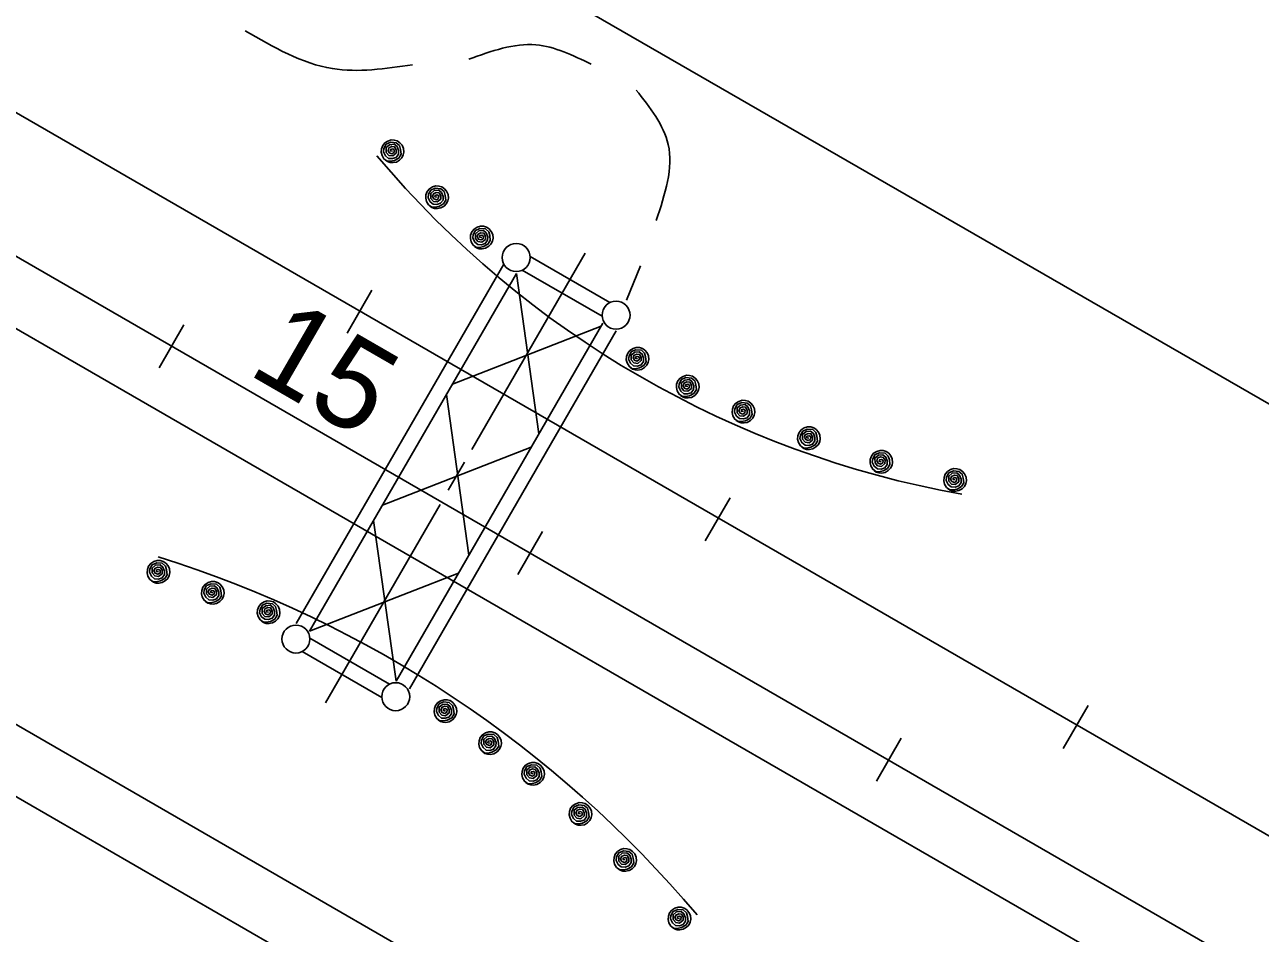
# Model space of a CAD drawing. Extents: x 36 to 2622, y -5330 to 219.
# Drawn here: x 617.89 to 659.11, y -5106.98 to -5076.66 of the extents above; entities that cross this region are included whole.
import ezdxf

# ---------------------------------------------------------------- set-up
doc = ezdxf.new("R2010")
doc.units = 0
doc.layers.add('2', color=7, linetype='Continuous')

msp = doc.modelspace()

# ---------------------------------------------------------------- linework, layer by layer
at = {"layer": '2'}
for p, q in [((699.623, -5134.156), (428.193, -4977.446)), ((700.667, -5132.348), (434.985, -4978.962)), ((693.9, -5144.068), (416.962, -4984.173)), ((692.86, -5145.872), (414.78, -4985.319)), ((661.896, -5090.759), (614.012, -5063.109)), ((702.741, -5128.756), (615.251, -5078.236)), ((636.594, -5084.285), (632.808, -5090.834)), ((637.414, -5085.931), (634.758, -5084.4)), ((626.948, -5096.646), (633.875, -5084.647)), ((637.154, -5086.382), (634.493, -5084.849)), ((638.44, -5084.703), (637.971, -5085.852)), ((627.398, -5096.902), (634.296, -5084.957)), ((634.296, -5084.957), (635.044, -5090.316)), ((628.644, -5086.956), (629.476, -5085.521)), ((622.378, -5088.111), (623.204, -5086.677)), ((630.281, -5098.566), (637.179, -5086.619)), ((630.73, -5098.824), (637.628, -5086.879)), ((632.161, -5088.654), (637.123, -5086.717)), ((631.96, -5089.001), (632.708, -5094.36)), ((629.825, -5092.695), (634.787, -5090.761)), ((632.563, -5091.262), (632.024, -5092.194)), ((631.754, -5092.668), (627.932, -5099.284)), ((640.592, -5093.883), (641.424, -5092.448)), ((629.532, -5093.209), (630.281, -5098.566)), ((634.344, -5095.007), (635.169, -5093.573)), ((627.398, -5096.902), (632.359, -5094.967)), ((630.065, -5098.664), (627.406, -5097.131)), ((629.804, -5099.113), (627.146, -5097.58)), ((652.541, -5100.81), (653.373, -5099.375)), ((646.311, -5101.903), (647.137, -5100.469))]:
    msp.add_line(p, q, dxfattribs=at)
for points in [[(630.162, -5080.884), (630.094, -5080.869), (630.098, -5080.822), (630.171, -5080.805), (630.223, -5080.84), (630.214, -5080.923), (630.139, -5080.965), (630.056, -5080.934), (630.013, -5080.855), (630.042, -5080.77), (630.137, -5080.726), (630.229, -5080.738), (630.287, -5080.834), (630.285, -5080.946), (630.168, -5081.04), (630.04, -5081.021), (629.954, -5080.922), (629.952, -5080.759), (630.067, -5080.663), (630.219, -5080.651), (630.314, -5080.728), (630.364, -5080.859), (630.362, -5080.976), (630.283, -5081.086), (630.16, -5081.127), (630.033, -5081.119), (629.929, -5081.034), (629.863, -5080.899), (629.877, -5080.786), (629.956, -5080.647), (630.104, -5080.582), (630.289, -5080.599), (630.397, -5080.695), (630.433, -5080.822), (630.452, -5080.982), (630.372, -5081.109), (630.227, -5081.188), (630.085, -5081.217), (629.977, -5081.207), (629.877, -5081.136), (629.813, -5081.025), (629.788, -5080.915), (629.794, -5080.805), (629.834, -5080.695), (629.909, -5080.603), (630.01, -5080.541), (630.121, -5080.505), (630.223, -5080.51), (630.322, -5080.539), (630.41, -5080.599), (630.481, -5080.684), (630.53, -5080.788), (630.541, -5080.911), (630.522, -5081.003), (630.472, -5081.102), (630.397, -5081.177), (630.291, -5081.242), (630.177, -5081.263), (630.083, -5081.258), (629.994, -5081.229), (629.925, -5081.179)], [(631.648, -5082.417), (631.579, -5082.403), (631.583, -5082.355), (631.656, -5082.338), (631.708, -5082.373), (631.7, -5082.457), (631.625, -5082.498), (631.542, -5082.467), (631.498, -5082.388), (631.527, -5082.303), (631.623, -5082.259), (631.714, -5082.271), (631.772, -5082.367), (631.77, -5082.48), (631.654, -5082.573), (631.525, -5082.554), (631.44, -5082.455), (631.438, -5082.292), (631.552, -5082.197), (631.704, -5082.184), (631.799, -5082.261), (631.849, -5082.392), (631.847, -5082.509), (631.768, -5082.619), (631.645, -5082.66), (631.519, -5082.652), (631.415, -5082.567), (631.348, -5082.432), (631.363, -5082.319), (631.442, -5082.18), (631.589, -5082.115), (631.774, -5082.132), (631.883, -5082.228), (631.918, -5082.355), (631.937, -5082.515), (631.858, -5082.642), (631.712, -5082.721), (631.571, -5082.75), (631.462, -5082.74), (631.363, -5082.669), (631.298, -5082.559), (631.273, -5082.448), (631.279, -5082.338), (631.319, -5082.228), (631.394, -5082.136), (631.496, -5082.074), (631.606, -5082.038), (631.708, -5082.043), (631.808, -5082.072), (631.895, -5082.132), (631.966, -5082.217), (632.016, -5082.322), (632.026, -5082.444), (632.008, -5082.536), (631.957, -5082.636), (631.883, -5082.711), (631.777, -5082.775), (631.662, -5082.796), (631.568, -5082.792), (631.479, -5082.762), (631.41, -5082.713)], [(633.137, -5083.761), (633.068, -5083.746), (633.072, -5083.699), (633.145, -5083.682), (633.197, -5083.717), (633.189, -5083.801), (633.114, -5083.842), (633.031, -5083.811), (632.987, -5083.732), (633.016, -5083.646), (633.112, -5083.603), (633.204, -5083.615), (633.262, -5083.711), (633.26, -5083.823), (633.143, -5083.917), (633.014, -5083.898), (632.929, -5083.798), (632.927, -5083.636), (633.041, -5083.541), (633.193, -5083.528), (633.289, -5083.605), (633.339, -5083.736), (633.337, -5083.852), (633.258, -5083.963), (633.135, -5084.004), (633.008, -5083.996), (632.904, -5083.911), (632.837, -5083.775), (632.852, -5083.663), (632.931, -5083.524), (633.079, -5083.459), (633.264, -5083.476), (633.372, -5083.572), (633.407, -5083.699), (633.426, -5083.859), (633.347, -5083.986), (633.202, -5084.065), (633.06, -5084.094), (632.952, -5084.083), (632.852, -5084.013), (632.788, -5083.902), (632.763, -5083.792), (632.769, -5083.682), (632.808, -5083.572), (632.883, -5083.48), (632.985, -5083.418), (633.095, -5083.382), (633.197, -5083.387), (633.297, -5083.416), (633.385, -5083.476), (633.455, -5083.561), (633.505, -5083.665), (633.516, -5083.788), (633.497, -5083.88), (633.447, -5083.979), (633.372, -5084.054), (633.266, -5084.119), (633.152, -5084.14), (633.058, -5084.135), (632.969, -5084.106), (632.9, -5084.056)], [(638.337, -5087.807), (638.269, -5087.792), (638.273, -5087.744), (638.346, -5087.728), (638.398, -5087.763), (638.389, -5087.847), (638.315, -5087.888), (638.231, -5087.857), (638.188, -5087.778), (638.217, -5087.693), (638.312, -5087.649), (638.404, -5087.661), (638.462, -5087.757), (638.46, -5087.869), (638.344, -5087.963), (638.215, -5087.944), (638.13, -5087.844), (638.127, -5087.682), (638.242, -5087.587), (638.394, -5087.574), (638.489, -5087.651), (638.539, -5087.782), (638.537, -5087.899), (638.458, -5088.009), (638.336, -5088.05), (638.208, -5088.042), (638.105, -5087.957), (638.038, -5087.822), (638.053, -5087.709), (638.132, -5087.57), (638.279, -5087.505), (638.464, -5087.522), (638.573, -5087.618), (638.608, -5087.744), (638.627, -5087.905), (638.548, -5088.032), (638.402, -5088.111), (638.26, -5088.14), (638.152, -5088.129), (638.053, -5088.059), (637.988, -5087.948), (637.963, -5087.838), (637.969, -5087.728), (638.009, -5087.618), (638.084, -5087.526), (638.186, -5087.464), (638.296, -5087.428), (638.398, -5087.432), (638.498, -5087.462), (638.585, -5087.522), (638.656, -5087.607), (638.706, -5087.711), (638.716, -5087.834), (638.697, -5087.926), (638.648, -5088.025), (638.573, -5088.1), (638.466, -5088.165), (638.352, -5088.186), (638.259, -5088.181), (638.169, -5088.152), (638.1, -5088.102)], [(640.01, -5088.737), (639.941, -5088.722), (639.946, -5088.674), (640.018, -5088.658), (640.07, -5088.693), (640.062, -5088.776), (639.987, -5088.818), (639.904, -5088.787), (639.86, -5088.708), (639.889, -5088.622), (639.985, -5088.579), (640.077, -5088.591), (640.135, -5088.687), (640.133, -5088.799), (640.016, -5088.893), (639.887, -5088.874), (639.802, -5088.774), (639.8, -5088.612), (639.914, -5088.516), (640.066, -5088.504), (640.162, -5088.581), (640.212, -5088.712), (640.21, -5088.828), (640.131, -5088.939), (640.008, -5088.98), (639.881, -5088.972), (639.777, -5088.887), (639.711, -5088.751), (639.725, -5088.639), (639.804, -5088.5), (639.952, -5088.435), (640.137, -5088.452), (640.245, -5088.547), (640.28, -5088.674), (640.299, -5088.835), (640.22, -5088.962), (640.075, -5089.041), (639.933, -5089.07), (639.825, -5089.059), (639.725, -5088.989), (639.661, -5088.878), (639.636, -5088.768), (639.642, -5088.658), (639.681, -5088.547), (639.756, -5088.456), (639.858, -5088.394), (639.968, -5088.358), (640.07, -5088.362), (640.17, -5088.391), (640.258, -5088.452), (640.328, -5088.537), (640.378, -5088.641), (640.389, -5088.764), (640.37, -5088.855), (640.32, -5088.955), (640.245, -5089.03), (640.139, -5089.095), (640.025, -5089.115), (639.931, -5089.111), (639.841, -5089.082), (639.773, -5089.032)], [(641.87, -5089.571), (641.801, -5089.556), (641.805, -5089.509), (641.878, -5089.492), (641.93, -5089.527), (641.922, -5089.61), (641.847, -5089.652), (641.764, -5089.621), (641.72, -5089.542), (641.749, -5089.457), (641.845, -5089.413), (641.936, -5089.425), (641.995, -5089.521), (641.993, -5089.633), (641.876, -5089.727), (641.747, -5089.708), (641.662, -5089.608), (641.66, -5089.446), (641.774, -5089.351), (641.926, -5089.338), (642.022, -5089.415), (642.072, -5089.546), (642.069, -5089.663), (641.99, -5089.773), (641.868, -5089.814), (641.741, -5089.806), (641.637, -5089.721), (641.57, -5089.586), (641.585, -5089.473), (641.664, -5089.334), (641.812, -5089.269), (641.997, -5089.286), (642.105, -5089.382), (642.14, -5089.509), (642.159, -5089.669), (642.08, -5089.796), (641.934, -5089.875), (641.793, -5089.904), (641.685, -5089.893), (641.585, -5089.823), (641.52, -5089.712), (641.495, -5089.602), (641.501, -5089.492), (641.541, -5089.382), (641.616, -5089.29), (641.718, -5089.228), (641.828, -5089.192), (641.93, -5089.197), (642.03, -5089.226), (642.117, -5089.286), (642.188, -5089.371), (642.238, -5089.475), (642.248, -5089.598), (642.23, -5089.69), (642.18, -5089.789), (642.105, -5089.864), (641.999, -5089.929), (641.884, -5089.95), (641.791, -5089.945), (641.701, -5089.916), (641.633, -5089.866)], [(644.054, -5090.457), (643.985, -5090.443), (643.99, -5090.395), (644.062, -5090.378), (644.114, -5090.413), (644.106, -5090.497), (644.031, -5090.538), (643.948, -5090.507), (643.904, -5090.428), (643.933, -5090.343), (644.029, -5090.299), (644.12, -5090.311), (644.179, -5090.407), (644.177, -5090.52), (644.06, -5090.613), (643.931, -5090.595), (643.846, -5090.495), (643.844, -5090.332), (643.958, -5090.237), (644.11, -5090.224), (644.206, -5090.301), (644.256, -5090.432), (644.254, -5090.549), (644.175, -5090.659), (644.052, -5090.7), (643.925, -5090.692), (643.821, -5090.607), (643.754, -5090.472), (643.769, -5090.359), (643.848, -5090.22), (643.996, -5090.155), (644.181, -5090.172), (644.289, -5090.268), (644.324, -5090.395), (644.343, -5090.555), (644.264, -5090.682), (644.118, -5090.761), (643.977, -5090.79), (643.869, -5090.78), (643.769, -5090.709), (643.705, -5090.599), (643.679, -5090.488), (643.686, -5090.378), (643.725, -5090.268), (643.8, -5090.176), (643.902, -5090.114), (644.012, -5090.079), (644.114, -5090.083), (644.214, -5090.112), (644.302, -5090.172), (644.372, -5090.257), (644.422, -5090.361), (644.433, -5090.484), (644.414, -5090.576), (644.364, -5090.676), (644.289, -5090.751), (644.183, -5090.815), (644.068, -5090.836), (643.975, -5090.832), (643.885, -5090.802), (643.817, -5090.753)], [(646.469, -5091.244), (646.4, -5091.229), (646.405, -5091.181), (646.477, -5091.164), (646.529, -5091.2), (646.521, -5091.283), (646.446, -5091.325), (646.363, -5091.293), (646.319, -5091.214), (646.348, -5091.129), (646.444, -5091.085), (646.536, -5091.098), (646.594, -5091.194), (646.592, -5091.306), (646.475, -5091.4), (646.346, -5091.381), (646.261, -5091.281), (646.259, -5091.119), (646.373, -5091.023), (646.525, -5091.011), (646.621, -5091.088), (646.671, -5091.218), (646.669, -5091.335), (646.59, -5091.445), (646.467, -5091.487), (646.34, -5091.479), (646.236, -5091.393), (646.169, -5091.258), (646.184, -5091.146), (646.263, -5091.006), (646.411, -5090.942), (646.596, -5090.958), (646.704, -5091.054), (646.74, -5091.181), (646.758, -5091.341), (646.679, -5091.468), (646.534, -5091.547), (646.392, -5091.576), (646.284, -5091.566), (646.184, -5091.495), (646.12, -5091.385), (646.095, -5091.275), (646.101, -5091.164), (646.14, -5091.054), (646.215, -5090.963), (646.317, -5090.9), (646.428, -5090.865), (646.529, -5090.869), (646.629, -5090.898), (646.717, -5090.958), (646.787, -5091.044), (646.837, -5091.148), (646.848, -5091.271), (646.829, -5091.362), (646.779, -5091.462), (646.704, -5091.537), (646.598, -5091.601), (646.484, -5091.622), (646.39, -5091.618), (646.301, -5091.589), (646.232, -5091.539)], [(648.932, -5091.851), (648.863, -5091.836), (648.868, -5091.788), (648.94, -5091.772), (648.992, -5091.807), (648.984, -5091.89), (648.909, -5091.932), (648.826, -5091.901), (648.782, -5091.822), (648.811, -5091.736), (648.907, -5091.693), (648.999, -5091.705), (649.057, -5091.801), (649.055, -5091.913), (648.938, -5092.007), (648.809, -5091.988), (648.724, -5091.888), (648.722, -5091.726), (648.836, -5091.63), (648.988, -5091.618), (649.084, -5091.695), (649.134, -5091.826), (649.132, -5091.942), (649.053, -5092.053), (648.93, -5092.094), (648.803, -5092.086), (648.699, -5092.001), (648.633, -5091.865), (648.647, -5091.753), (648.726, -5091.614), (648.874, -5091.549), (649.059, -5091.566), (649.167, -5091.662), (649.202, -5091.788), (649.221, -5091.949), (649.142, -5092.075), (648.996, -5092.155), (648.855, -5092.184), (648.747, -5092.173), (648.647, -5092.103), (648.582, -5091.992), (648.558, -5091.882), (648.564, -5091.772), (648.603, -5091.662), (648.678, -5091.57), (648.78, -5091.508), (648.89, -5091.472), (648.992, -5091.476), (649.092, -5091.506), (649.18, -5091.566), (649.25, -5091.651), (649.3, -5091.755), (649.311, -5091.878), (649.292, -5091.97), (649.242, -5092.069), (649.167, -5092.144), (649.061, -5092.209), (648.947, -5092.23), (648.853, -5092.225), (648.764, -5092.196), (648.695, -5092.146)], [(622.353, -5094.917), (622.284, -5094.903), (622.289, -5094.855), (622.361, -5094.838), (622.413, -5094.873), (622.405, -5094.957), (622.33, -5094.998), (622.247, -5094.967), (622.203, -5094.888), (622.232, -5094.803), (622.328, -5094.759), (622.42, -5094.771), (622.478, -5094.867), (622.476, -5094.98), (622.36, -5095.073), (622.231, -5095.054), (622.145, -5094.954), (622.143, -5094.792), (622.258, -5094.697), (622.409, -5094.684), (622.505, -5094.761), (622.555, -5094.892), (622.553, -5095.009), (622.474, -5095.119), (622.351, -5095.16), (622.224, -5095.152), (622.12, -5095.067), (622.054, -5094.932), (622.068, -5094.819), (622.147, -5094.68), (622.295, -5094.615), (622.48, -5094.632), (622.588, -5094.728), (622.624, -5094.855), (622.642, -5095.015), (622.563, -5095.142), (622.418, -5095.221), (622.276, -5095.25), (622.168, -5095.239), (622.068, -5095.169), (622.004, -5095.059), (621.979, -5094.948), (621.985, -5094.838), (622.024, -5094.728), (622.099, -5094.636), (622.201, -5094.574), (622.312, -5094.538), (622.413, -5094.543), (622.513, -5094.572), (622.601, -5094.632), (622.672, -5094.717), (622.721, -5094.821), (622.732, -5094.944), (622.713, -5095.036), (622.663, -5095.136), (622.588, -5095.21), (622.482, -5095.275), (622.368, -5095.296), (622.274, -5095.292), (622.185, -5095.262), (622.116, -5095.213)], [(624.165, -5095.616), (624.096, -5095.601), (624.101, -5095.554), (624.173, -5095.537), (624.225, -5095.572), (624.217, -5095.656), (624.142, -5095.697), (624.059, -5095.666), (624.015, -5095.587), (624.044, -5095.502), (624.14, -5095.458), (624.232, -5095.471), (624.29, -5095.566), (624.288, -5095.678), (624.171, -5095.772), (624.042, -5095.753), (623.957, -5095.654), (623.955, -5095.491), (624.069, -5095.396), (624.221, -5095.383), (624.317, -5095.46), (624.367, -5095.591), (624.365, -5095.708), (624.286, -5095.818), (624.163, -5095.86), (624.036, -5095.851), (623.932, -5095.766), (623.865, -5095.631), (623.88, -5095.518), (623.959, -5095.379), (624.107, -5095.314), (624.292, -5095.331), (624.4, -5095.427), (624.436, -5095.554), (624.454, -5095.714), (624.375, -5095.841), (624.23, -5095.92), (624.088, -5095.949), (623.98, -5095.939), (623.88, -5095.868), (623.816, -5095.757), (623.791, -5095.647), (623.797, -5095.537), (623.836, -5095.427), (623.911, -5095.335), (624.013, -5095.273), (624.124, -5095.238), (624.225, -5095.242), (624.325, -5095.271), (624.413, -5095.331), (624.483, -5095.416), (624.533, -5095.52), (624.544, -5095.643), (624.525, -5095.735), (624.475, -5095.834), (624.4, -5095.909), (624.294, -5095.974), (624.18, -5095.995), (624.086, -5095.99), (623.997, -5095.961), (623.928, -5095.912)], [(626.027, -5096.267), (625.958, -5096.253), (625.962, -5096.205), (626.035, -5096.188), (626.087, -5096.224), (626.079, -5096.307), (626.004, -5096.348), (625.921, -5096.317), (625.877, -5096.238), (625.906, -5096.153), (626.002, -5096.109), (626.093, -5096.122), (626.152, -5096.217), (626.15, -5096.33), (626.033, -5096.423), (625.904, -5096.405), (625.819, -5096.305), (625.817, -5096.142), (625.931, -5096.047), (626.083, -5096.034), (626.179, -5096.111), (626.229, -5096.242), (626.226, -5096.359), (626.148, -5096.469), (626.025, -5096.511), (625.898, -5096.502), (625.794, -5096.417), (625.727, -5096.282), (625.742, -5096.169), (625.821, -5096.03), (625.969, -5095.966), (626.154, -5095.982), (626.262, -5096.078), (626.297, -5096.205), (626.316, -5096.365), (626.237, -5096.492), (626.091, -5096.571), (625.95, -5096.6), (625.842, -5096.59), (625.742, -5096.519), (625.677, -5096.409), (625.652, -5096.298), (625.659, -5096.188), (625.698, -5096.078), (625.773, -5095.986), (625.875, -5095.924), (625.985, -5095.889), (626.087, -5095.893), (626.187, -5095.922), (626.274, -5095.982), (626.345, -5096.068), (626.395, -5096.172), (626.405, -5096.294), (626.387, -5096.386), (626.337, -5096.486), (626.262, -5096.561), (626.156, -5096.625), (626.041, -5096.646), (625.948, -5096.642), (625.858, -5096.613), (625.79, -5096.562)], [(631.926, -5099.562), (631.858, -5099.548), (631.862, -5099.5), (631.935, -5099.483), (631.987, -5099.519), (631.978, -5099.602), (631.904, -5099.643), (631.82, -5099.612), (631.777, -5099.533), (631.806, -5099.448), (631.901, -5099.404), (631.993, -5099.417), (632.051, -5099.512), (632.049, -5099.625), (631.933, -5099.718), (631.804, -5099.699), (631.718, -5099.6), (631.716, -5099.437), (631.831, -5099.342), (631.982, -5099.329), (632.078, -5099.406), (632.128, -5099.537), (632.126, -5099.654), (632.047, -5099.764), (631.924, -5099.806), (631.797, -5099.797), (631.693, -5099.712), (631.627, -5099.577), (631.641, -5099.465), (631.72, -5099.325), (631.868, -5099.261), (632.053, -5099.277), (632.161, -5099.373), (632.197, -5099.5), (632.216, -5099.66), (632.136, -5099.787), (631.991, -5099.866), (631.849, -5099.895), (631.741, -5099.885), (631.641, -5099.814), (631.577, -5099.704), (631.552, -5099.593), (631.558, -5099.483), (631.598, -5099.373), (631.673, -5099.281), (631.774, -5099.219), (631.885, -5099.184), (631.987, -5099.188), (632.087, -5099.217), (632.174, -5099.277), (632.245, -5099.363), (632.294, -5099.467), (632.305, -5099.589), (632.286, -5099.681), (632.236, -5099.781), (632.161, -5099.855), (632.055, -5099.92), (631.941, -5099.941), (631.847, -5099.937), (631.758, -5099.908), (631.689, -5099.858)], [(633.416, -5100.633), (633.347, -5100.619), (633.351, -5100.571), (633.424, -5100.555), (633.476, -5100.59), (633.468, -5100.673), (633.393, -5100.715), (633.31, -5100.684), (633.266, -5100.604), (633.295, -5100.519), (633.391, -5100.475), (633.482, -5100.488), (633.541, -5100.584), (633.538, -5100.696), (633.422, -5100.789), (633.293, -5100.771), (633.208, -5100.671), (633.206, -5100.509), (633.32, -5100.413), (633.472, -5100.4), (633.568, -5100.477), (633.618, -5100.609), (633.615, -5100.725), (633.536, -5100.835), (633.414, -5100.877), (633.287, -5100.869), (633.183, -5100.783), (633.116, -5100.648), (633.131, -5100.536), (633.21, -5100.396), (633.357, -5100.332), (633.543, -5100.349), (633.651, -5100.444), (633.686, -5100.571), (633.705, -5100.731), (633.626, -5100.858), (633.48, -5100.937), (633.339, -5100.966), (633.231, -5100.956), (633.131, -5100.885), (633.066, -5100.775), (633.041, -5100.665), (633.048, -5100.555), (633.087, -5100.444), (633.162, -5100.353), (633.264, -5100.29), (633.374, -5100.255), (633.476, -5100.259), (633.576, -5100.288), (633.663, -5100.349), (633.734, -5100.434), (633.784, -5100.538), (633.794, -5100.661), (633.776, -5100.752), (633.726, -5100.852), (633.651, -5100.927), (633.545, -5100.991), (633.43, -5101.012), (633.337, -5101.008), (633.247, -5100.979), (633.179, -5100.929)], [(634.853, -5101.655), (634.784, -5101.64), (634.789, -5101.592), (634.861, -5101.576), (634.913, -5101.611), (634.905, -5101.694), (634.83, -5101.736), (634.747, -5101.705), (634.703, -5101.626), (634.732, -5101.541), (634.828, -5101.497), (634.92, -5101.509), (634.978, -5101.605), (634.976, -5101.717), (634.859, -5101.811), (634.731, -5101.792), (634.645, -5101.692), (634.643, -5101.53), (634.758, -5101.434), (634.909, -5101.422), (635.005, -5101.499), (635.055, -5101.63), (635.053, -5101.746), (634.974, -5101.857), (634.851, -5101.898), (634.724, -5101.89), (634.62, -5101.805), (634.554, -5101.669), (634.568, -5101.557), (634.647, -5101.418), (634.795, -5101.353), (634.98, -5101.37), (635.088, -5101.466), (635.124, -5101.592), (635.142, -5101.753), (635.063, -5101.88), (634.918, -5101.959), (634.776, -5101.988), (634.668, -5101.977), (634.568, -5101.907), (634.504, -5101.796), (634.479, -5101.686), (634.485, -5101.576), (634.524, -5101.466), (634.599, -5101.374), (634.701, -5101.312), (634.812, -5101.276), (634.913, -5101.28), (635.013, -5101.31), (635.101, -5101.37), (635.172, -5101.455), (635.221, -5101.559), (635.232, -5101.682), (635.213, -5101.774), (635.163, -5101.873), (635.088, -5101.948), (634.982, -5102.013), (634.868, -5102.034), (634.774, -5102.029), (634.685, -5102), (634.616, -5101.95)], [(636.434, -5102.999), (636.365, -5102.984), (636.37, -5102.936), (636.442, -5102.92), (636.495, -5102.955), (636.486, -5103.038), (636.411, -5103.08), (636.328, -5103.049), (636.284, -5102.97), (636.313, -5102.884), (636.409, -5102.841), (636.501, -5102.853), (636.559, -5102.949), (636.557, -5103.061), (636.44, -5103.155), (636.311, -5103.136), (636.226, -5103.036), (636.224, -5102.874), (636.339, -5102.778), (636.49, -5102.766), (636.586, -5102.843), (636.636, -5102.974), (636.634, -5103.09), (636.555, -5103.2), (636.432, -5103.242), (636.305, -5103.234), (636.201, -5103.149), (636.135, -5103.013), (636.149, -5102.901), (636.228, -5102.762), (636.376, -5102.697), (636.561, -5102.714), (636.669, -5102.809), (636.705, -5102.936), (636.723, -5103.097), (636.644, -5103.223), (636.499, -5103.302), (636.357, -5103.332), (636.249, -5103.321), (636.149, -5103.25), (636.085, -5103.14), (636.06, -5103.03), (636.066, -5102.92), (636.106, -5102.809), (636.18, -5102.718), (636.282, -5102.655), (636.393, -5102.62), (636.495, -5102.624), (636.594, -5102.653), (636.682, -5102.714), (636.752, -5102.799), (636.802, -5102.903), (636.813, -5103.026), (636.794, -5103.117), (636.744, -5103.217), (636.669, -5103.292), (636.563, -5103.356), (636.449, -5103.377), (636.355, -5103.373), (636.266, -5103.344), (636.197, -5103.294)], [(637.924, -5104.532), (637.855, -5104.517), (637.859, -5104.469), (637.932, -5104.453), (637.984, -5104.488), (637.976, -5104.571), (637.901, -5104.613), (637.817, -5104.582), (637.774, -5104.503), (637.803, -5104.417), (637.899, -5104.374), (637.99, -5104.386), (638.048, -5104.482), (638.046, -5104.594), (637.93, -5104.688), (637.801, -5104.669), (637.716, -5104.569), (637.714, -5104.407), (637.828, -5104.311), (637.98, -5104.299), (638.075, -5104.376), (638.125, -5104.507), (638.123, -5104.623), (638.044, -5104.734), (637.922, -5104.775), (637.795, -5104.767), (637.691, -5104.682), (637.624, -5104.546), (637.639, -5104.434), (637.718, -5104.295), (637.865, -5104.23), (638.051, -5104.247), (638.159, -5104.342), (638.194, -5104.469), (638.213, -5104.63), (638.134, -5104.757), (637.988, -5104.836), (637.847, -5104.865), (637.738, -5104.854), (637.639, -5104.784), (637.574, -5104.673), (637.549, -5104.563), (637.555, -5104.453), (637.595, -5104.342), (637.67, -5104.251), (637.772, -5104.189), (637.882, -5104.153), (637.984, -5104.157), (638.084, -5104.186), (638.171, -5104.247), (638.242, -5104.332), (638.292, -5104.436), (638.302, -5104.559), (638.284, -5104.65), (638.234, -5104.75), (638.159, -5104.825), (638.053, -5104.89), (637.938, -5104.91), (637.845, -5104.906), (637.755, -5104.877), (637.686, -5104.827)], [(639.735, -5106.485), (639.667, -5106.471), (639.671, -5106.423), (639.744, -5106.406), (639.796, -5106.441), (639.787, -5106.525), (639.712, -5106.566), (639.629, -5106.535), (639.586, -5106.456), (639.615, -5106.371), (639.711, -5106.327), (639.802, -5106.34), (639.86, -5106.435), (639.858, -5106.547), (639.742, -5106.641), (639.613, -5106.623), (639.527, -5106.523), (639.525, -5106.36), (639.64, -5106.265), (639.792, -5106.252), (639.887, -5106.329), (639.937, -5106.46), (639.935, -5106.577), (639.856, -5106.687), (639.733, -5106.729), (639.606, -5106.72), (639.503, -5106.635), (639.436, -5106.5), (639.45, -5106.387), (639.529, -5106.248), (639.677, -5106.184), (639.862, -5106.2), (639.971, -5106.296), (640.006, -5106.423), (640.025, -5106.583), (639.946, -5106.71), (639.8, -5106.789), (639.659, -5106.818), (639.55, -5106.808), (639.45, -5106.737), (639.386, -5106.627), (639.361, -5106.516), (639.367, -5106.406), (639.407, -5106.296), (639.482, -5106.204), (639.584, -5106.142), (639.694, -5106.106), (639.796, -5106.111), (639.896, -5106.14), (639.983, -5106.2), (640.054, -5106.285), (640.104, -5106.39), (640.114, -5106.512), (640.095, -5106.604), (640.045, -5106.704), (639.971, -5106.779), (639.864, -5106.843), (639.75, -5106.864), (639.656, -5106.86), (639.567, -5106.831), (639.498, -5106.78)]]:
    msp.add_lwpolyline(points, dxfattribs=at)
for centre in [(634.29, -5084.429), (637.621, -5086.352), (626.94, -5097.161), (630.271, -5099.085)]:
    msp.add_circle(centre, 0.467, dxfattribs=at)
for centre, radius, start, end in [((655.012, -5059.71), 33.14, 220.0491, 259.8292), ((610.836, -5131.243), 38.581, 40.157, 72.6466)]:
    msp.add_arc(centre, radius, start, end, dxfattribs=at)
for points in [[(625.243, -5076.859), (628.159, -5078.124), (630.832, -5077.993)], [(632.706, -5077.81), (634.947, -5077.331), (636.792, -5077.98)], [(638.292, -5078.839), (639.359, -5080.653), (638.962, -5083.195)]]:
    msp.add_spline(points, degree=3, dxfattribs=at)

# ---------------------------------------------------------------- texts
msp.add_text('15', height=2.9955, rotation=329.9961, dxfattribs=at).set_placement((625.278, -5088.285))

doc.saveas('drawing.dxf')
